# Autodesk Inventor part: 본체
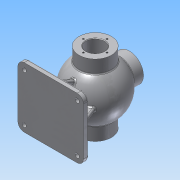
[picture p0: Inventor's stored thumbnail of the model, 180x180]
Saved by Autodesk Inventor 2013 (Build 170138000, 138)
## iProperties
Created: 2018-06
Part Number: 본체
Material: 알루미늄 6061
Document SubType Name: Modeling
Designer: Administrator
Density: 2.71 g/cm^3
Mass: 1509.74 g
Surface Area: 1154.49 cm^2
Volume: 557.1 cm^3
Author: Administrator
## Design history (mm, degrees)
sketch "스케치1"
  geometry: L1 (-68, 0)-(68, 0); A1 r 53 centre (0, 0) between (53, 0) and (-53, 0); A2 r 43 centre (0, 0) between (43, 0) and (-43, 0); 2 further points
  constraints: 4 coincident, 4 point on circle, 4 point on line, 2 centre point, 2 end point, 1 horizontal, 1 midpoint
  dimensions: "d0" = 136 distance of L1.start L1.end; "d1" = 106 diameter of A1; "d2" = 86 diameter of A2
revolve "회전1" sketch "스케치1" stored, may be unused: angle "d3" = 90 deg
node "작업 평면1"
sketch "스케치2"
  geometry: C1 r 31 at (0, 0); 1 further point
  constraints: 1 centre point, 1 coincident
  dimensions: "d5" = 62 diameter of C1
extrude "돌출1" join sketch "스케치2" stored distance "d6" = 10; taper "d7" = 0 deg
hole "구멍1" diameter "d10" = 35; stored, may be unused: countersink angle "d14" = 90 deg, drill point angle "d16" = 118 deg; dims "d8" = 10, "d9" = 10, "d11" = 6, "d12" = 4, "d13" = 2, "d15" = 8
sketch "스케치3"
  geometry: C1 r 17.5 at (0, 0) reference; 1 further point
  constraints: 1 vertical alignment
  dimensions: "d17" = 22.5 distance of C1.centre point (0, 22.5)
hole "구멍2" sketch "스케치3" at (0, 22.5) diameter "d18" = 3.242; stored, may be unused: countersink angle "d22" = 90 deg, drill point angle "d24" = 118 deg; dims "d19" = 12, "d20" = 4, "d21" = 2, "d23" = 15
node "작업 평면2"
sketch "스케치4"
  geometry: C1 r 27 at (0, 0); 1 further point
  constraints: 1 centre point, 1 coincident
  dimensions: "d30" = 54 diameter of C1
extrude "돌출2" join sketch "스케치4" stored distance "d31" = 10; taper "d32" = 0 deg
hole "구멍3" diameter "d35" = 26; stored, may be unused: countersink angle "d39" = 90 deg, drill point angle "d41" = 0 deg; dims "d33" = 10, "d34" = 10, "d36" = 12, "d37" = 4, "d38" = 2, "d40" = 60
sketch "스케치5"
  geometry: C1 r 13 at (0, 0) reference; 1 further point
  constraints: 1 vertical alignment
  dimensions: "d42" = 20 distance of C1.centre point (0, 20)
hole "구멍4" sketch "스케치5" at (0, 20) diameter "d43" = 3.242; stored, may be unused: countersink angle "d47" = 90 deg, drill point angle "d49" = 118 deg; dims "d44" = 9, "d45" = 4, "d46" = 2, "d48" = 11
chamfer "모따기1" distance "d53" = 1; stored, may be unused: second distance "d54" = 2, angle "d55" = 45 deg
node "작업 평면3"
sketch "스케치6"
  geometry: L1 (62.5, 57.5)-(-62.5, 57.5); L2 (-62.5, 57.5)-(-62.5, -57.5); L3 (-62.5, -57.5)-(62.5, -57.5); L4 (62.5, -57.5)-(62.5, 57.5); L5 (62.5, 57.5)-(-62.5, -57.5); L6 (-62.5, 57.5)-(62.5, -57.5); 1 further point
  constraints: 12 end point, 2 midpoint, 2 parallel, 1 horizontal, 1 perpendicular
  dimensions: "d57" = 125 distance of L3.end L2.end; "d58" = 115 distance of L2.end L1.end
extrude "돌출3" join sketch "스케치6" distance "d59" = 10; taper "d60" = 0 deg
sketch "스케치7"
  geometry: L1 (4, -47.5)-(-4, -47.5); L2 (-4, -47.5)-(-4, 47.5); L3 (-4, 47.5)-(4, 47.5); L4 (4, 47.5)-(4, -47.5); L5 (4, -47.5)-(-4, 47.5); L6 (-4, -47.5)-(4, 47.5); L7 (-52.5, -4)-(52.5, -4); L8 (52.5, -4)-(52.5, 4); L9 (52.5, 4)-(-52.5, 4); L10 (-52.5, 4)-(-52.5, -4); L11 (-52.5, -4)-(52.5, 4); L12 (52.5, -4)-(-52.5, 4); 1 further point
  constraints: 24 end point, 4 midpoint, 4 parallel, 2 horizontal, 2 perpendicular
  dimensions: "d61" = 8 distance of L2.end L3.end; "d62" = 95 distance of L1.end L2.end; "d63" = 105 distance of L9.end L8.end; "d64" = 8 distance of L8.end L7.end
extrude "돌출4" join sketch "스케치7" stored distance "d65" = 10; taper "d66" = 0 deg
extrude "돌출5" join sketch "스케치7" stored distance "d67" = 10; taper "d68" = 0 deg
feature "면 기울기1" dims angle "d69" = 22 deg
hole "구멍5" diameter "d72" = 35; stored, may be unused: countersink angle "d76" = 90 deg, drill point angle "d78" = 0 deg; dims "d70" = 10, "d71" = 10, "d73" = 9, "d74" = 4, "d75" = 2, "d77" = 16
hole "구멍6" diameter "d81" = 35; stored, may be unused: countersink angle "d85" = 90 deg, drill point angle "d87" = 0 deg; dims "d79" = 10, "d80" = 10, "d82" = 9, "d83" = 37, "d84" = 1.75, "d86" = 20
fillet "모깎기2" dims "d88" = 12
hole "구멍7" diameter "d91" = 8; stored, may be unused: countersink angle "d95" = 90 deg, drill point angle "d97" = 0 deg; dims "d89" = 10, "d90" = 10, "d92" = 9, "d93" = 12, "d94" = 3, "d96" = 10
fillet "모깎기3" dims "d98" = 3
fillet "모깎기4" dims "d99" = 3
fillet "모깎기5" dims "d100" = 3
node "작업 평면4"
sketch "스케치8"
  geometry: L1 (0, -27)-(17.714, -27) reference; L2 (0, -27)-(0, 27) reference; 2 further points
  constraints: 1 other
  dimensions: "d101" = 27 distance from line of point (10, 0) L1; "d102" = 10 distance from line of point (10, 0) L2
feature "엠보싱1" sketch "스케치8" dims "d0" = 136, "d1" = 106, "d2" = 86, "d103" = 0.5, "d104" = 0
sketch "스케치9"
  geometry: C1 r 17.5 at (0, 0) reference; 1 further point
  constraints: 1 vertical alignment
  dimensions: "d105" = 24 distance of C1.centre point (0, 24)
hole "구멍8" sketch "스케치9" at (0, 24) diameter "d106" = 3.242; stored, may be unused: countersink angle "d110" = 90 deg, drill point angle "d112" = 118 deg; dims "d107" = 16, "d108" = 12, "d109" = 3, "d111" = 19
node "솔리드1"
pattern_circular "원형 패턴1" dims angle "d26" = 360 deg
mirror "대칭1"
pattern_circular "원형 패턴2" dims angle "d51" = 360 deg
mirror "대칭2"
mirror "대칭3"
pattern_circular "원형 패턴3" dims angle "d114" = 360 deg
other parameters: "d4" = 68, "d29" = 65, "d56" = -85
